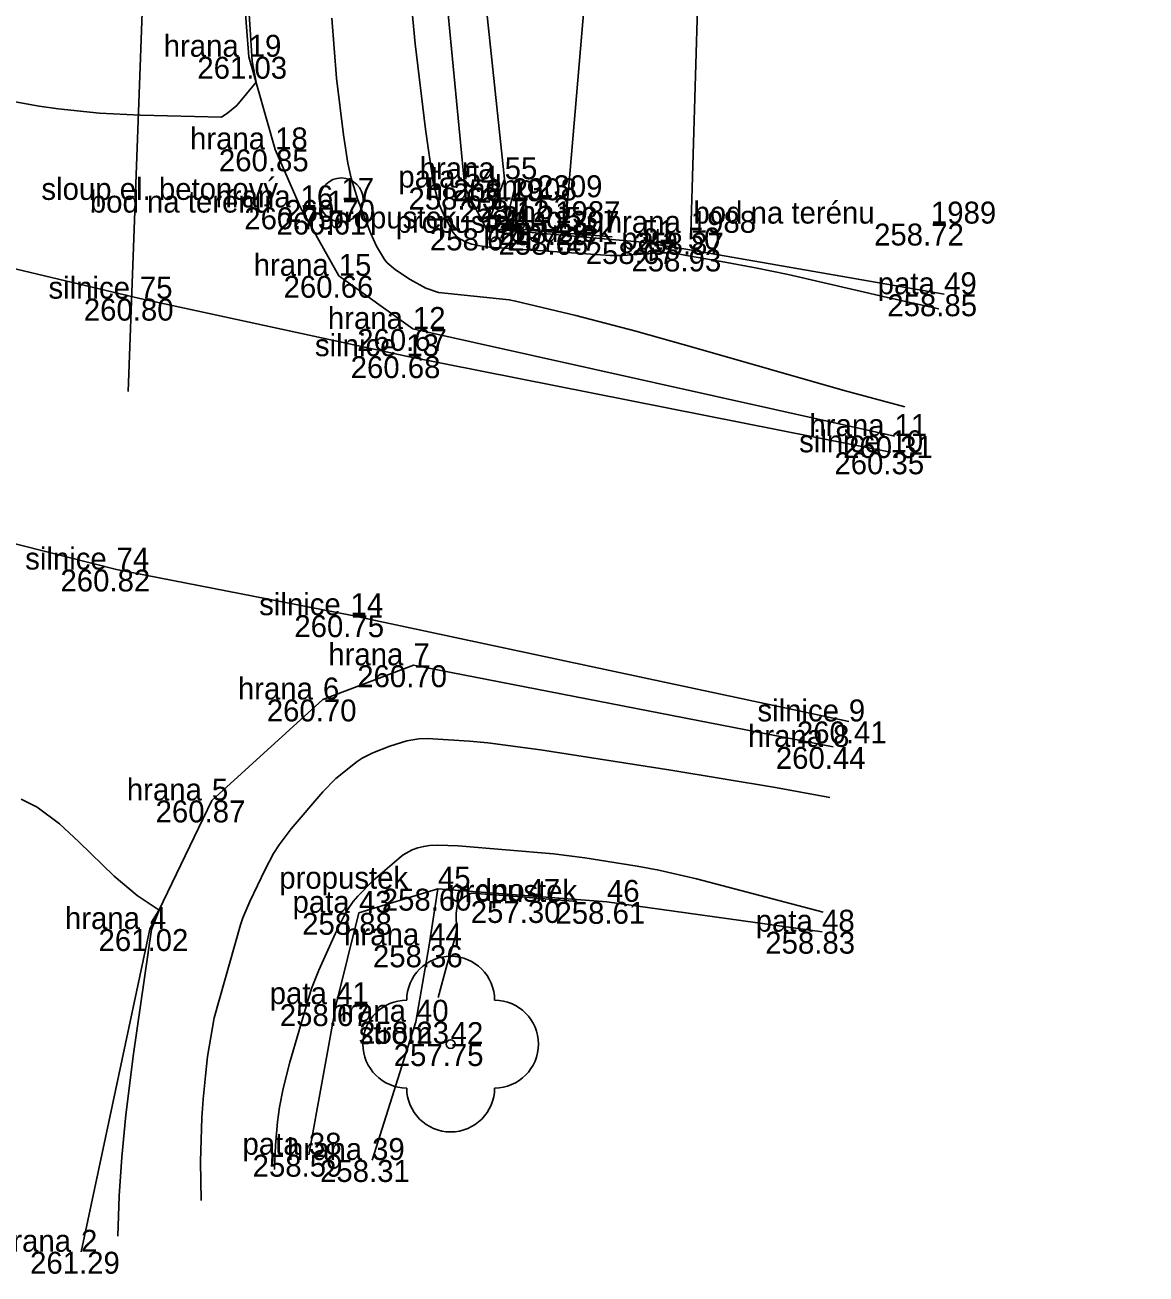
# Model space of a CAD drawing. Extents: x -567962 to -566460, y -1093720 to -1089838.
# Drawn here: x -567527.96 to -567502.42, y -1093523.14 to -1093494.69 of the extents above; entities that cross this region are included whole.
import ezdxf

# ---------------------------------------------------------------- set-up
doc = ezdxf.new("R2010")
doc.units = 0
for name, color, linetype in [('0_osa hráze', 7, 'Continuous'), ('bod_znacka', 7, 'Continuous'), ('cislo_bodu', 7, 'Continuous'), ('hlavni_vrst', 7, 'Continuous'), ('hrana_L', 7, 'Continuous'), ('kod_bodu', 7, 'Continuous'), ('norm_vrst', 7, 'Continuous'), ('ostatni', 7, 'Continuous'), ('propustky', 7, 'Continuous'), ('silnice', 7, 'Continuous'), ('stromy', 7, 'Continuous'), ('Vrstva 1', 7, 'Continuous'), ('vyska_bodu', 7, 'Continuous')]:
    doc.layers.add(name, color=color, linetype=linetype)

# ---------------------------------------------------------------- blocks, each defined once
blk = doc.blocks.new('6.01')
at = {"layer": 'Vrstva 1'}
blk.add_circle((0, 0), 0.05, dxfattribs=at)

msp = doc.modelspace()

# ---------------------------------------------------------------- linework, layer by layer
at = {"layer": '0_osa hráze'}
msp.add_lwpolyline([(-567525.15, -1093490.7), (-567525.61, -1093503.034)], dxfattribs=at)
at = {"layer": 'bod_znacka'}
for p, q in [((-567522.86, -1093495.41), (-567522.86, -1093495.41)), ((-567522.26, -1093497.52), (-567522.26, -1093497.52)), ((-567517.03, -1093498.2), (-567517.03, -1093498.2)), ((-567517.94, -1093498.39), (-567517.94, -1093498.39)), ((-567521.68, -1093498.84), (-567521.68, -1093498.84)), ((-567520.75, -1093498.67), (-567520.75, -1093498.67)), ((-567516.87, -1093498.68), (-567516.87, -1093498.68)), ((-567516.29, -1093498.61), (-567516.29, -1093498.61)), ((-567521.07, -1093498.96), (-567521.07, -1093498.96)), ((-567517.45, -1093499.32), (-567517.45, -1093499.32)), ((-567515.9, -1093499.42), (-567515.9, -1093499.42)), ((-567515.88, -1093499.2), (-567515.88, -1093499.2)), ((-567515.65, -1093499.33), (-567515.65, -1093499.33)), ((-567512.79, -1093499.42), (-567512.79, -1093499.42)), ((-567507.32, -1093499.21), (-567507.32, -1093499.21)), ((-567513.9, -1093499.63), (-567513.9, -1093499.63)), ((-567512.86, -1093499.8), (-567512.86, -1093499.8)), ((-567520.81, -1093500.4), (-567520.81, -1093500.4)), ((-567507.02, -1093500.82), (-567507.02, -1093500.82)), ((-567525.34, -1093500.92), (-567525.34, -1093500.92)), ((-567519.12, -1093501.61), (-567519.12, -1093501.61)), ((-567519.27, -1093502.23), (-567519.27, -1093502.23)), ((-567508.15, -1093504.05), (-567508.15, -1093504.05)), ((-567508.24, -1093504.42), (-567508.24, -1093504.42)), ((-567525.87, -1093507.09), (-567525.87, -1093507.09)), ((-567520.54, -1093508.13), (-567520.54, -1093508.13)), ((-567519.11, -1093509.27), (-567519.11, -1093509.27)), ((-567521.17, -1093510.05), (-567521.17, -1093510.05)), ((-567509.19, -1093510.55), (-567509.19, -1093510.55)), ((-567509.55, -1093511.13), (-567509.55, -1093511.13)), ((-567523.7, -1093512.35), (-567523.7, -1093512.35)), ((-567518.55, -1093514.36), (-567518.55, -1093514.36)), ((-567516.51, -1093514.64), (-567516.51, -1093514.64)), ((-567514.7, -1093514.66), (-567514.7, -1093514.66)), ((-567520.35, -1093514.91), (-567520.35, -1093514.91)), ((-567525.11, -1093515.28), (-567525.11, -1093515.28)), ((-567509.8, -1093515.34), (-567509.8, -1093515.34)), ((-567518.75, -1093515.65), (-567518.75, -1093515.65)), ((-567520.87, -1093516.99), (-567520.87, -1093516.99)), ((-567519.05, -1093517.39), (-567519.05, -1093517.39)), ((-567518.26, -1093517.9), (-567518.26, -1093517.9)), ((-567521.49, -1093520.42), (-567521.49, -1093520.42)), ((-567520.05, -1093520.54), (-567520.05, -1093520.54)), ((-567526.68, -1093522.63), (-567526.68, -1093522.63))]:
    msp.add_line(p, q, dxfattribs=at)
at = {"layer": 'hlavni_vrst'}
for points in [[(-567507.916, -1093503.382), (-567509.328, -1093503.004), (-567512.671, -1093502.044), (-567514.039, -1093501.663), (-567515.408, -1093501.3), (-567516.781, -1093500.977), (-567516.926, -1093500.95), (-567518.536, -1093500.777), (-567518.826, -1093500.678), (-567519.185, -1093500.485), (-567519.517, -1093500.266), (-567519.705, -1093500.102), (-567519.768, -1093500.031), (-567519.951, -1093499.727), (-567520.089, -1093499.423), (-567520.373, -1093498.667), (-567520.524, -1093498.175), (-567520.604, -1093497.832), (-567520.703, -1093497.189), (-567520.857, -1093495.898), (-567520.969, -1093494.533)], [(-567523.947, -1093521.466), (-567523.962, -1093520.571), (-567523.928, -1093519.583), (-567523.897, -1093519.152), (-567523.848, -1093518.623), (-567523.796, -1093518.184), (-567523.645, -1093517.299), (-567523.05, -1093515.181), (-567522.992, -1093515.021), (-567522.836, -1093514.651), (-567522.485, -1093513.919), (-567522.292, -1093513.56), (-567522.165, -1093513.359), (-567521.892, -1093512.997), (-567521.169, -1093512.152), (-567520.874, -1093511.851), (-567520.393, -1093511.465), (-567520.279, -1093511.39), (-567520.032, -1093511.265), (-567519.647, -1093511.115), (-567519.255, -1093510.99), (-567518.983, -1093510.943), (-567518.784, -1093510.941), (-567517.828, -1093510.996), (-567517.414, -1093511.041), (-567516.217, -1093511.199), (-567513.241, -1093511.662), (-567510.864, -1093512.052), (-567509.619, -1093512.284)]]:
    msp.add_lwpolyline(points, dxfattribs=at)
at = {"layer": 'hrana_L'}
for p, q in [((-567525.27, -1093463.58), (-567522.86, -1093495.41)), ((-567517.94, -1093498.39), (-567518.44, -1093493.13)), ((-567517.58, -1093493.03), (-567517.03, -1093498.2)), ((-567522.26, -1093497.52), (-567522.86, -1093495.41)), ((-567521.68, -1093498.84), (-567522.26, -1093497.52)), ((-567517.45, -1093499.32), (-567517.03, -1093498.2)), ((-567517.45, -1093499.32), (-567517.94, -1093498.39)), ((-567520.81, -1093500.4), (-567521.68, -1093498.84)), ((-567512.86, -1093499.8), (-567513.9, -1093499.63)), ((-567507.02, -1093500.82), (-567512.86, -1093499.8)), ((-567520.81, -1093500.4), (-567519.12, -1093501.61)), ((-567519.12, -1093501.61), (-567508.15, -1093504.05)), ((-567521.17, -1093510.05), (-567519.11, -1093509.27)), ((-567509.55, -1093511.13), (-567519.11, -1093509.27)), ((-567523.7, -1093512.35), (-567521.17, -1093510.05)), ((-567525.11, -1093515.28), (-567523.7, -1093512.35)), ((-567520.35, -1093514.91), (-567518.55, -1093514.36)), ((-567518.75, -1093515.65), (-567518.55, -1093514.36)), ((-567509.8, -1093515.34), (-567514.7, -1093514.66)), ((-567520.87, -1093516.99), (-567520.35, -1093514.91)), ((-567526.68, -1093522.63), (-567525.11, -1093515.28)), ((-567519.05, -1093517.39), (-567518.75, -1093515.65)), ((-567521.49, -1093520.42), (-567520.87, -1093516.99)), ((-567520.05, -1093520.54), (-567519.05, -1093517.39))]:
    msp.add_line(p, q, dxfattribs=at)
for points in [[(-567512.79, -1093499.42), (-567512.53, -1093490.77), (-567515.14, -1093473.2), (-567516.86, -1093463), (-567517.05, -1093457.43), (-567510.86, -1093456.87), (-567507.33, -1093455.1), (-567502.54, -1093450.69), (-567502.42, -1093448.31), (-567503.88, -1093440.95), (-567522.38, -1093412.95), (-567526.32, -1093385.81), (-567534.77, -1093360.4), (-567542.63, -1093336.01), (-567576.2, -1093233.72), (-567608.17, -1093145.58), (-567635.77, -1093066.14), (-567667.57, -1092974.74), (-567711.16, -1092852.65), (-567720.26, -1092825.93), (-567727.08, -1092790.56), (-567728.5, -1092756.42), (-567723.8, -1092688.57)], [(-567517.74, -1093456.46), (-567518.94, -1093463.92), (-567517.26, -1093473.36), (-567514.9, -1093490.5), (-567515.65, -1093499.33)]]:
    msp.add_lwpolyline(points, dxfattribs=at)
at = {"layer": 'norm_vrst'}
for points in [[(-567528.989, -1093493.346), (-567530.274, -1093495.303), (-567530.526, -1093495.445), (-567529.631, -1093495.998), (-567529.145, -1093496.17), (-567528.598, -1093496.341), (-567528.179, -1093496.436), (-567527.635, -1093496.535), (-567527.202, -1093496.598), (-567526.257, -1093496.691), (-567525.325, -1093496.744), (-567523.48, -1093496.788), (-567523.336, -1093496.684), (-567523.131, -1093496.517), (-567522.694, -1093495.992), (-567522.779, -1093495.509), (-567522.886, -1093493.83)], [(-567507.137, -1093501.153), (-567508.311, -1093500.895), (-567510.574, -1093500.373), (-567511.319, -1093500.218), (-567512.052, -1093500.083), (-567512.89, -1093499.936), (-567513.188, -1093499.877), (-567513.488, -1093499.878), (-567514.339, -1093499.935), (-567514.628, -1093499.935), (-567517.377, -1093499.747), (-567517.592, -1093499.719), (-567517.781, -1093499.681), (-567517.906, -1093499.633), (-567518.039, -1093499.566), (-567518.122, -1093499.509), (-567518.213, -1093499.405), (-567518.452, -1093498.937), (-567518.534, -1093498.732), (-567518.656, -1093498.273), (-567518.835, -1093497.062), (-567519.07, -1093495.113), (-567519.185, -1093493.899)], [(-567514.583, -1093499.513), (-567516.333, -1093499.372), (-567516.722, -1093499.327), (-567516.758, -1093499.316), (-567516.846, -1093499.245), (-567516.928, -1093499.162), (-567516.944, -1093499.023), (-567516.903, -1093498.802), (-567516.796, -1093498.391)], [(-567525.842, -1093522.273), (-567525.808, -1093521.356), (-567525.753, -1093520.472), (-567525.659, -1093519.514), (-567525.486, -1093518.122), (-567525.072, -1093515.286), (-567524.901, -1093514.846), (-567525.399, -1093514.515), (-567525.922, -1093514.071), (-567526.729, -1093513.289), (-567527.173, -1093512.883), (-567527.678, -1093512.505), (-567528.042, -1093512.321)], [(-567522.272, -1093520.753), (-567522.247, -1093520.205), (-567522.202, -1093519.67), (-567522.161, -1093519.339), (-567522.076, -1093518.915), (-567521.922, -1093518.311), (-567521.516, -1093516.915), (-567521.427, -1093516.635), (-567521.266, -1093516.215), (-567520.884, -1093515.374), (-567520.696, -1093514.991), (-567520.612, -1093514.844), (-567520.482, -1093514.655), (-567520.372, -1093514.527), (-567520.016, -1093514.164), (-567519.435, -1093513.661), (-567519.343, -1093513.592), (-567519.134, -1093513.474), (-567519.011, -1093513.431), (-567518.873, -1093513.397), (-567518.742, -1093513.376), (-567518.56, -1093513.366), (-567518.088, -1093513.38), (-567515.916, -1093513.566), (-567515.207, -1093513.659), (-567514.015, -1093513.848), (-567513.519, -1093513.937), (-567512.662, -1093514.132), (-567509.774, -1093514.896)], [(-567518.544, -1093516.842), (-567518.34, -1093516.08), (-567518.16, -1093515.471), (-567518.129, -1093515.307), (-567518.131, -1093514.916), (-567518.115, -1093514.757), (-567518.06, -1093514.628), (-567517.944, -1093514.543), (-567517.782, -1093514.465), (-567516.839, -1093514.53), (-567515.388, -1093514.652)]]:
    msp.add_lwpolyline(points, dxfattribs=at)
at = {"layer": 'propustky'}
for p, q in [((-567517.45, -1093499.32), (-567513.9, -1093499.63)), ((-567514.7, -1093514.66), (-567518.55, -1093514.36))]:
    msp.add_line(p, q, dxfattribs=at)
at = {"layer": 'silnice'}
for p, q in [((-567525.34, -1093500.92), (-567536.3, -1093498.31)), ((-567525.34, -1093500.92), (-567519.27, -1093502.23)), ((-567519.27, -1093502.23), (-567508.24, -1093504.42)), ((-567537.68, -1093504.1), (-567525.87, -1093507.09)), ((-567520.54, -1093508.13), (-567525.87, -1093507.09)), ((-567520.54, -1093508.13), (-567509.19, -1093510.55))]:
    msp.add_line(p, q, dxfattribs=at)
at = {"layer": 'stromy'}
msp.add_circle((-567518.26, -1093517.9), 0.1, dxfattribs=at)
for centre, start, end in [((-567518.26, -1093516.9), 0, 180), ((-567519.26, -1093517.9), 90, 270), ((-567517.26, -1093517.9), 270, 90), ((-567518.26, -1093518.9), 180, 0)]:
    msp.add_arc(centre, 1, start, end, dxfattribs=at)

# ---------------------------------------------------------------- block references
at = {"layer": 'ostatni', "xscale": 10, "yscale": 10}
msp.add_blockref('6.01', (-567520.75, -1093498.67), dxfattribs=at)

# ---------------------------------------------------------------- texts
at = {"layer": 'cislo_bodu'}
for s, p in [('19', (-567522.86, -1093495.41)), ('18', (-567522.26, -1093497.52)), ('55', (-567517.03, -1093498.2)), ('54', (-567517.94, -1093498.39)), ('17', (-567520.75, -1093498.67)), ('2308', (-567516.87, -1093498.68)), ('2309', (-567516.29, -1093498.61)), ('16', (-567521.68, -1093498.84)), ('1', (-567521.07, -1093498.96)), ('52', (-567517.45, -1093499.32)), ('1987', (-567515.88, -1093499.2)), ('53', (-567515.65, -1093499.33)), ('1989', (-567507.32, -1093499.21)), ('2307', (-567515.9, -1093499.42)), ('51', (-567513.9, -1093499.63)), ('1988', (-567512.79, -1093499.42)), ('50', (-567512.86, -1093499.8)), ('15', (-567520.81, -1093500.4)), ('75', (-567525.34, -1093500.92)), ('49', (-567507.02, -1093500.82)), ('12', (-567519.12, -1093501.61)), ('13', (-567519.27, -1093502.23)), ('11', (-567508.15, -1093504.05)), ('10', (-567508.24, -1093504.42)), ('74', (-567525.87, -1093507.09)), ('14', (-567520.54, -1093508.13)), ('7', (-567519.11, -1093509.27)), ('6', (-567521.17, -1093510.05)), ('9', (-567509.19, -1093510.55)), ('8', (-567509.55, -1093511.13)), ('5', (-567523.7, -1093512.35)), ('45', (-567518.55, -1093514.36)), ('47', (-567516.51, -1093514.64)), ('46', (-567514.7, -1093514.66)), ('43', (-567520.35, -1093514.91)), ('4', (-567525.11, -1093515.28)), ('48', (-567509.8, -1093515.34)), ('44', (-567518.75, -1093515.65)), ('41', (-567520.87, -1093516.99)), ('40', (-567519.05, -1093517.39)), ('42', (-567518.26, -1093517.9)), ('38', (-567521.49, -1093520.42)), ('39', (-567520.05, -1093520.54)), ('2', (-567526.68, -1093522.63))]:
    msp.add_text(s, height=0.5, dxfattribs=at).set_placement(p)
at = {"layer": 'kod_bodu'}
for s, p in [('hrana', (-567524.797, -1093495.41)), ('hrana', (-567524.197, -1093497.52)), ('hrana', (-567518.967, -1093498.2)), ('pata', (-567519.452, -1093498.39)), ('sloup el. betonový', (-567527.583, -1093498.67)), ('hrana', (-567518.807, -1093498.68)), ('dno', (-567517.471, -1093498.61)), ('bod na terénu', (-567526.479, -1093498.96)), ('hrana', (-567523.617, -1093498.84)), ('propustek', (-567521.064, -1093499.32)), ('dno', (-567517.061, -1093499.2)), ('dno', (-567516.831, -1093499.33)), ('bod na terénu', (-567512.729, -1093499.21)), ('propustek', (-567519.514, -1093499.42)), ('propustek', (-567517.514, -1093499.63)), ('hrana', (-567514.727, -1093499.42)), ('pata', (-567514.372, -1093499.8)), ('hrana', (-567522.747, -1093500.4)), ('silnice', (-567527.422, -1093500.92)), ('pata', (-567508.532, -1093500.82)), ('hrana', (-567521.057, -1093501.61)), ('silnice', (-567521.352, -1093502.23)), ('hrana', (-567510.087, -1093504.05)), ('silnice', (-567510.322, -1093504.42)), ('silnice', (-567527.952, -1093507.09)), ('silnice', (-567522.622, -1093508.13)), ('hrana', (-567521.047, -1093509.27)), ('hrana', (-567523.107, -1093510.05)), ('silnice', (-567511.272, -1093510.55)), ('hrana', (-567511.487, -1093511.13)), ('hrana', (-567525.637, -1093512.35)), ('propustek', (-567522.164, -1093514.36)), ('propustek', (-567518.314, -1093514.66)), ('dno', (-567517.691, -1093514.64)), ('pata', (-567521.862, -1093514.91)), ('hrana', (-567527.047, -1093515.28)), ('pata', (-567511.312, -1093515.34)), ('hrana', (-567520.687, -1093515.65)), ('pata', (-567522.382, -1093516.99)), ('hrana', (-567520.987, -1093517.39)), ('strom', (-567520.354, -1093517.9)), ('pata', (-567523.002, -1093520.42)), ('hrana', (-567521.987, -1093520.54)), ('hrana', (-567528.617, -1093522.63))]:
    msp.add_text(s, height=0.5, dxfattribs=at).set_placement(p)
at = {"layer": 'vyska_bodu'}
for s, p in [('261.03', (-567524.031, -1093495.91)), ('260.85', (-567523.539, -1093498.02)), ('258.19', (-567518.203, -1093498.7)), ('258.63', (-567519.221, -1093498.89)), ('260.75', (-567522.961, -1093499.34)), ('260.70', (-567522.029, -1093499.17)), ('258.12', (-567518.055, -1093499.18)), ('257.53', (-567517.585, -1093499.11)), ('260.61', (-567522.229, -1093499.46)), ('258.67', (-567518.733, -1093499.82)), ('258.66', (-567517.17, -1093499.92)), ('257.29', (-567517.163, -1093499.7)), ('257.27', (-567516.947, -1093499.83)), ('258.87', (-567514.085, -1093499.92)), ('258.72', (-567508.615, -1093499.71)), ('258.67', (-567515.183, -1093500.13)), ('258.93', (-567514.141, -1093500.3)), ('260.66', (-567522.066, -1093500.9)), ('258.85', (-567508.313, -1093501.32)), ('260.80', (-567526.617, -1093501.42)), ('260.67', (-567520.39, -1093502.11)), ('260.68', (-567520.538, -1093502.73)), ('260.31', (-567509.321, -1093504.55)), ('260.35', (-567509.519, -1093504.92)), ('260.82', (-567527.149, -1093507.59)), ('260.75', (-567521.821, -1093508.63)), ('260.70', (-567520.389, -1093509.77)), ('260.70', (-567522.449, -1093510.55)), ('260.41', (-567510.373, -1093511.05)), ('260.44', (-567510.853, -1093511.63)), ('260.87', (-567524.981, -1093512.85)), ('258.60', (-567519.829, -1093514.86)), ('257.30', (-567517.803, -1093515.14)), ('258.61', (-567515.873, -1093515.16)), ('258.88', (-567521.643, -1093515.41)), ('261.02', (-567526.281, -1093515.78)), ('258.83', (-567511.093, -1093515.84)), ('258.36', (-567520.031, -1093516.15)), ('258.67', (-567522.153, -1093517.49)), ('258.23', (-567520.343, -1093517.89)), ('257.75', (-567519.557, -1093518.4)), ('258.59', (-567522.771, -1093520.92)), ('258.31', (-567521.235, -1093521.04)), ('261.29', (-567527.841, -1093523.13))]:
    msp.add_text(s, height=0.5, dxfattribs=at).set_placement(p)

doc.saveas('drawing.dxf')
